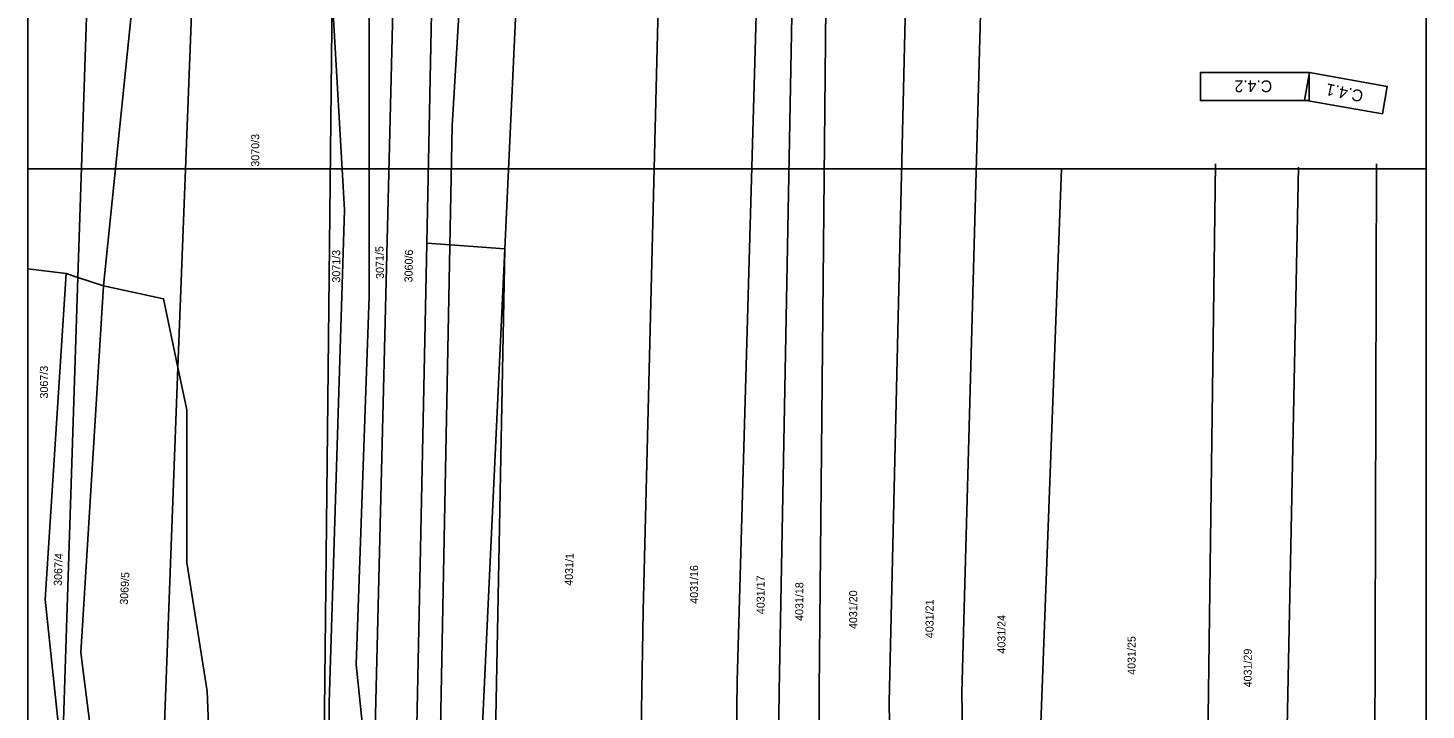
# Model space of a CAD drawing. Extents: x -534410 to -534262, y -1190162 to -1189584.
# Drawn here: x -534410.1 to -534261.6, y -1189746.9 to -1189674.5 of the extents above; entities that cross this region are included whole.
import ezdxf

# ---------------------------------------------------------------- set-up
doc = ezdxf.new("R2010")
doc.units = 0
for name, color, linetype in [('_KN_Město_Hluk', 7, 'Continuous'), ('_KN_Povodí_Moravy', 7, 'Continuous'), ('_N_osa', 7, 'Continuous'), ('_rámeček', 7, 'Continuous'), ('_rámeček_mřížka', 7, 'Continuous'), ('_severka', 7, 'Continuous'), ('Hranice parcel', 7, 'Continuous'), ('Parcelní čísla', 7, 'Continuous')]:
    doc.layers.add(name, color=color, linetype=linetype)

msp = doc.modelspace()

# ---------------------------------------------------------------- linework, layer by layer
at = {"layer": '_KN_Město_Hluk'}
for p, q in [((-534359.48, -1189697.97), (-534356.61, -1189636.93)), ((-534366.56, -1189638.19), (-534367.77, -1189697.34)), ((-534367.77, -1189697.34), (-534364.28, -1189697.61)), ((-534364.28, -1189697.61), (-534359.48, -1189697.97))]:
    msp.add_line(p, q, dxfattribs=at)
at = {"layer": '_KN_Povodí_Moravy'}
msp.add_line((-534367.77, -1189697.34), (-534369.14, -1189764.19), dxfattribs=at)
for points in [[(-534359.48, -1189697.97), (-534364.28, -1189697.61), (-534367.77, -1189697.34)], [(-534362.34, -1189901.56), (-534362.6, -1189764.35), (-534359.48, -1189697.97)]]:
    msp.add_lwpolyline(points, dxfattribs=at)
at = {"layer": '_N_osa'}
msp.add_lwpolyline([(-534351.95, -1189940.72), (-534356.84, -1189928.92), (-534363.29, -1189912.04), (-534365.92, -1189888.84), (-534366.71, -1189846.73), (-534366.46, -1189820.49), (-534366.39, -1189779.5), (-534366.3, -1189748.87), (-534365.06, -1189684.89), (-534363.19, -1189653.56), (-534361.33, -1189627.82)], dxfattribs=at)
at = {"layer": '_rámeček'}
msp.add_line((-534410.13, -1189584.47), (-534410.13, -1190161.97), dxfattribs=at)
msp.add_lwpolyline([(-534410.13, -1190161.97), (-534261.63, -1190161.97), (-534261.63, -1189584.47)], dxfattribs=at)
for points in [[(-534410.13, -1189584.47), (-534261.63, -1189584.47), (-534261.63, -1189689.47), (-534410.13, -1189689.47)], [(-534274.04, -1189682.21), (-534285.59, -1189682.21), (-534285.59, -1189679.24), (-534274.04, -1189679.24)], [(-534410.13, -1189689.47), (-534261.63, -1189689.47), (-534261.63, -1189794.47), (-534410.13, -1189794.47)]]:
    msp.add_lwpolyline(points, close=True, dxfattribs=at)
at = {"layer": '_rámeček_mřížka'}
for p, q in [((-534410.13, -1189584.47), (-534410.13, -1190161.97)), ((-534407.13, -1189689.47), (-534410.13, -1189689.47)), ((-534407.13, -1189689.47), (-534410.13, -1189689.47)), ((-534264.63, -1189689.47), (-534261.63, -1189689.47))]:
    msp.add_line(p, q, dxfattribs=at)
msp.add_lwpolyline([(-534410.13, -1190161.97), (-534261.63, -1190161.97), (-534261.63, -1189584.47)], dxfattribs=at)
for points in [[(-534274.04, -1189682.21), (-534285.59, -1189682.21), (-534285.59, -1189679.24), (-534274.04, -1189679.24)], [(-534266.26, -1189683.62), (-534274.53, -1189682.17), (-534274.01, -1189679.24), (-534265.74, -1189680.7)]]:
    msp.add_lwpolyline(points, close=True, dxfattribs=at)
at = {"layer": 'Hranice parcel'}
for p, q in [((-534404.82, -1189701), (-534402.64, -1189633.7)), ((-534394.19, -1189710.57), (-534391.41, -1189637.73)), ((-534359.48, -1189697.97), (-534356.61, -1189636.93)), ((-534366.56, -1189638.19), (-534367.77, -1189697.34)), ((-534371.04, -1189658.4), (-534373.49, -1189759.21)), ((-534378.67, -1189750.28), (-534377.8, -1189671.05)), ((-534369.14, -1189764.19), (-534367.77, -1189697.34)), ((-534406.48, -1189752.31), (-534404.82, -1189701)), ((-534404.82, -1189701), (-534406.08, -1189700.59)), ((-534402.1, -1189701.89), (-534404.82, -1189701)), ((-534398.3, -1189817.87), (-534394.19, -1189710.57))]:
    msp.add_line(p, q, dxfattribs=at)
for points in [[(-534347.07, -1189935.15), (-534347.12, -1189900.1), (-534346.3, -1189826.77), (-534344.77, -1189736.43), (-534342.85, -1189658.07), (-534338.33, -1189584.47)], [(-534338.84, -1189942.48), (-534336.49, -1189881.83), (-534334.78, -1189743.85), (-534331.69, -1189634.65)], [(-534334.89, -1189942.46), (-534332.03, -1189880.06), (-534330.32, -1189744.92), (-534328.5, -1189646.74), (-534327.9, -1189634.55)], [(-534330.63, -1189942.43), (-534326.4, -1189862.47), (-534326.07, -1189744.82), (-534325.13, -1189646.79), (-534324.46, -1189634.65)], [(-534402.1, -1189701.89), (-534396.03, -1189642.33), (-534395.58, -1189636.23)], [(-534373.49, -1189759.21), (-534375.27, -1189742.09), (-534373.87, -1189702.99), (-534373.87, -1189662.03), (-534374.42, -1189646.7)], [(-534323.08, -1189942.39), (-534320.68, -1189906.36), (-534317.14, -1189842.3), (-534318.66, -1189746.11), (-534316.5, -1189653.71)], [(-534314.47, -1189942.34), (-534311.69, -1189899.83), (-534309.24, -1189848.85), (-534310.92, -1189745.14), (-534308.43, -1189653.71)], [(-534378.12, -1189750.26), (-534378.12, -1189746.17), (-534376.49, -1189693.82), (-534377.8, -1189671.05)], [(-534301.62, -1189830.03), (-534301.89, -1189795.41), (-534302.54, -1189748.37), (-534300.35, -1189689.47)], [(-534285.48, -1189830.14), (-534284.81, -1189750.3), (-534284, -1189688.91)], [(-534284.68, -1189943.89), (-534282.37, -1189910.46), (-534280.12, -1189888.37), (-534278.75, -1189838.65), (-534276.86, -1189771.85), (-534276.43, -1189752.24), (-534275.19, -1189689.29)], [(-534268.75, -1189786.35), (-534267.08, -1189751.92), (-534266.88, -1189688.91)], [(-534367.77, -1189697.34), (-534364.28, -1189697.61), (-534359.48, -1189697.97)], [(-534359.48, -1189697.97), (-534362.6, -1189764.35), (-534362.34, -1189901.56)], [(-534359.48, -1189697.97), (-534360.42, -1189747.8), (-534359.17, -1189788.69), (-534356.86, -1189843.2), (-534358.53, -1189915.98)], [(-534406.08, -1189700.59), (-534410.13, -1189700.07)], [(-534406.48, -1189752.31), (-534408.29, -1189735.19), (-534406.08, -1189700.59)], [(-534398.3, -1189817.87), (-534398.2, -1189776.76), (-534402.83, -1189754), (-534404.51, -1189740.82), (-534402.1, -1189701.89)], [(-534394.19, -1189710.57), (-534395.72, -1189703.26), (-534402.1, -1189701.89)], [(-534390.92, -1189749.37), (-534391.09, -1189744.93), (-534393.26, -1189731.27), (-534393.26, -1189715.05), (-534394.19, -1189710.57)]]:
    msp.add_lwpolyline(points, dxfattribs=at)

# ---------------------------------------------------------------- texts
at = {"layer": '_severka'}
for s, rotation, p in [('C.4.2', 180.1465, (-534277.97, -1189680.06)), ('C.4.1', 168.5042, (-534268.2, -1189681.17))]:
    msp.add_text(s, height=1.25, rotation=rotation, dxfattribs=at).set_placement(p)
at = {"layer": 'Parcelní čísla'}
for s, rotation, p in [('3070/3', 90, (-534385.56, -1189689.23)), ('3071/3', 90, (-534376.96, -1189701.54)), ('3071/5', 91, (-534372.31, -1189701.14)), ('3060/6', 89, (-534369.29, -1189701.52)), ('3067/3', 90, (-534408, -1189713.85)), ('3067/4', 88, (-534406.54, -1189733.76)), ('4031/1', 88, (-534352.28, -1189733.75)), ('3069/5', 87, (-534399.53, -1189735.77)), ('4031/16', 90, (-534338.95, -1189735.65)), ('4031/17', 90, (-534331.88, -1189736.75)), ('4031/18', 90, (-534327.77, -1189737.47)), ('4031/20', 90, (-534322.05, -1189738.33)), ('4031/21', 90, (-534313.94, -1189739.3)), ('4031/24', 90, (-534306.3, -1189740.94)), ('4031/25', 90, (-534292.48, -1189743.19)), ('4031/29', 90, (-534280.14, -1189744.52))]:
    msp.add_text(s, height=0.85, rotation=rotation, dxfattribs=at).set_placement(p)

doc.saveas('drawing.dxf')
